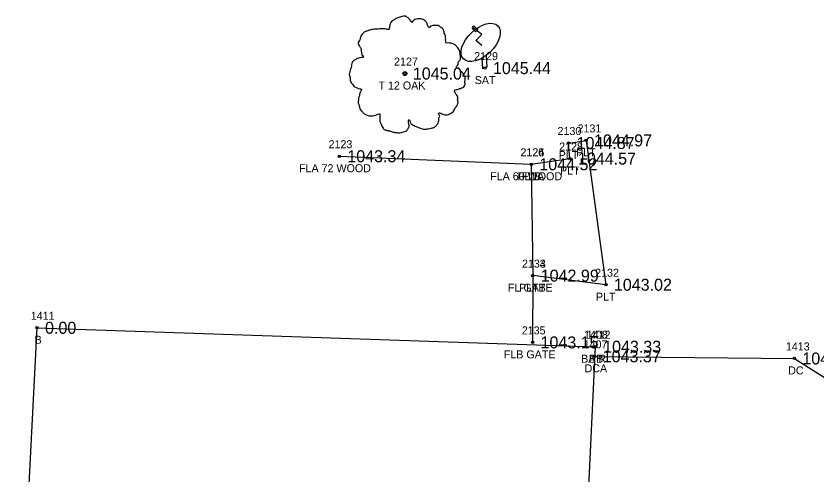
# Model space of a CAD drawing. Extents: x 1578957 to 1581675, y 1115963 to 1120391.
# Drawn here: x 1579631.3 to 1579731.3, y 1117805.4 to 1117862.7 of the extents above; entities that cross this region are included whole.
import ezdxf

# ---------------------------------------------------------------- set-up
doc = ezdxf.new("R2010")
doc.units = 0
for name, color, linetype in [('RD_EX_Bldg', 7, 'Continuous'), ('RD_EX_Bldg_txCode', 7, 'Continuous'), ('RD_EX_BldgApp', 7, 'Continuous'), ('RD_EX_BldgApp_txCode', 7, 'Continuous'), ('RD_EX_Conc', 7, 'Continuous'), ('RD_EX_Conc_txCode', 7, 'Continuous'), ('RD_EX_Fence_Other', 7, 'Continuous'), ('RD_EX_Fence_Other_txCode', 7, 'Continuous'), ('RD_EX_TX_Bldg_ELEV', 7, 'Continuous'), ('RD_EX_TX_BldgApp_ELEV', 7, 'Continuous'), ('RD_EX_TX_Conc_ELEV', 7, 'Continuous'), ('RD_EX_TX_Fence_Other_ELEV', 7, 'Continuous'), ('RD_EX_TX_VEG_ELEV', 7, 'Continuous'), ('RD_EX_VEG', 7, 'Continuous'), ('RD_EX_VEG_txCode', 7, 'Continuous'), ('RD_SMD_Locator', 7, 'Continuous')]:
    doc.layers.add(name, color=color, linetype=linetype)

msp = doc.modelspace()

# ---------------------------------------------------------------- linework, layer by layer
at = {"layer": 'RD_EX_Bldg'}
msp.add_lwpolyline([(1579703.654, 1117821.358), (1579701.175, 1117768.74), (1579631.267, 1117772.317), (1579633.897, 1117823.728), (1579703.654, 1117821.358)], dxfattribs=at)
at = {"layer": 'RD_EX_BldgApp'}
for p, q in [((1579688.717, 1117860.753), (1579688.325, 1117861.141)), ((1579689.503, 1117860.438), (1579688.39, 1117861.273)), ((1579688.568, 1117861.436), (1579688.992, 1117861.07)), ((1579688.601, 1117861.177), (1579688.601, 1117861.177)), ((1579688.716, 1117861.157), (1579688.716, 1117861.157)), ((1579688.993, 1117861.071), (1579688.717, 1117860.753)), ((1579688.736, 1117859.67), (1579689.503, 1117860.438)), ((1579689.503, 1117859.057), (1579688.736, 1117859.67)), ((1579689.503, 1117857.493), (1579689.58, 1117856.15)), ((1579690.04, 1117857.781), (1579690.117, 1117856.323))]:
    msp.add_line(p, q, dxfattribs=at)
msp.add_lwpolyline([(1579695.676, 1117844.189), (1579700.503, 1117844.906), (1579700.337, 1117846.851), (1579702.514, 1117847.178), (1579704.996, 1117829.116), (1579695.851, 1117830.253)], dxfattribs=at)
msp.add_ellipse((1579689.35, 1117859.44), major_axis=(-2.149, -2.072), ratio=0.564687, dxfattribs=at)
msp.add_ellipse((1579688.45, 1117861.285), major_axis=(0.099, 0.164), ratio=0.846225, start_param=6.138676, end_param=9.218032, dxfattribs=at)
at = {"layer": 'RD_EX_Conc'}
msp.add_lwpolyline([(1579703.598, 1117820.153), (1579728.553, 1117819.89), (1579733.569, 1117816.721), (1579737.087, 1117813.155), (1579748.821, 1117810.274), (1579774.526, 1117806.485), (1579776.381, 1117807.018)], dxfattribs=at)
at = {"layer": 'RD_EX_Fence_Other'}
msp.add_lwpolyline([(1579671.678, 1117845.198), (1579695.676, 1117844.189), (1579695.676, 1117844.189), (1579695.851, 1117830.253), (1579695.828, 1117821.899)], dxfattribs=at)
at = {"layer": 'RD_EX_VEG'}
for centre, radius in [((1579679.867, 1117855.546), 0.25), ((1579679.855, 1117855.527), 0.0001)]:
    msp.add_circle(centre, radius, dxfattribs=at)
for points in [[(1579679.999, 1117862.713), (1579679.699, 1117862.738), (1579679.374, 1117862.638), (1579679.124, 1117862.539), (1579678.9, 1117862.464), (1579678.675, 1117862.364), (1579678.375, 1117862.189), (1579678.15, 1117861.989), (1579678.025, 1117861.739), (1579677.975, 1117861.514), (1579677.925, 1117861.239), (1579677.925, 1117861.064), (1579677.8, 1117861.039), (1579677.65, 1117861.064), (1579677.4, 1117861.139), (1579677.15, 1117861.139), (1579676.9, 1117861.139), (1579676.551, 1117861.114), (1579676.201, 1117861.114), (1579675.926, 1117861.064), (1579675.601, 1117861.014), (1579675.226, 1117860.889), (1579674.876, 1117860.764), (1579674.576, 1117860.514), (1579674.327, 1117860.04), (1579674.202, 1117859.69), (1579674.052, 1117859.44), (1579674.202, 1117858.99), (1579674.377, 1117858.64), (1579674.401, 1117858.44), (1579674.476, 1117858.016), (1579674.576, 1117857.791), (1579674.701, 1117857.591), (1579674.626, 1117857.566), (1579674.252, 1117857.516), (1579673.952, 1117857.416), (1579673.527, 1117857.191), (1579673.302, 1117856.966), (1579673.202, 1117856.641), (1579673.177, 1117856.291), (1579673.077, 1117856.091), (1579673.002, 1117855.816), (1579672.977, 1117855.741), (1579672.927, 1117855.417), (1579673.027, 1117854.967), (1579673.052, 1117854.617), (1579673.177, 1117854.392), (1579673.327, 1117854.217), (1579673.502, 1117853.967), (1579673.902, 1117853.742), (1579674.227, 1117853.642), (1579674.426, 1117853.617), (1579674.252, 1117853.118), (1579674.202, 1117852.768), (1579674.077, 1117852.368), (1579674.077, 1117852.293), (1579674.027, 1117851.818), (1579674.177, 1117851.493), (1579674.252, 1117851.119), (1579674.426, 1117850.894), (1579674.701, 1117850.594), (1579675.026, 1117850.369), (1579675.526, 1117850.244), (1579675.926, 1117850.269), (1579676.501, 1117850.444), (1579676.75, 1117850.519), (1579676.725, 1117850.344), (1579676.75, 1117849.969), (1579676.75, 1117849.544), (1579676.9, 1117849.219), (1579677, 1117848.944), (1579677.15, 1117848.695), (1579677.475, 1117848.47), (1579677.875, 1117848.395), (1579678.3, 1117848.245), (1579678.75, 1117848.17), (1579679.249, 1117848.145), (1579679.849, 1117848.295), (1579680.124, 1117848.42), (1579680.224, 1117848.595), (1579680.424, 1117848.969), (1579680.374, 1117849.194), (1579680.399, 1117849.794), (1579680.499, 1117849.619), (1579680.674, 1117849.269), (1579681.174, 1117848.969), (1579681.573, 1117848.795), (1579682.048, 1117848.645), (1579682.348, 1117848.57), (1579682.823, 1117848.645), (1579683.198, 1117848.72), (1579683.572, 1117848.845), (1579683.872, 1117849.119), (1579684.047, 1117849.394), (1579684.097, 1117849.669), (1579684.172, 1117850.044), (1579684.222, 1117850.219)], [(1579684.222, 1117850.219), (1579684.147, 1117850.394), (1579684.097, 1117850.644), (1579684.172, 1117850.619), (1579684.347, 1117850.569), (1579684.622, 1117850.444), (1579684.847, 1117850.369), (1579685.172, 1117850.394), (1579685.447, 1117850.494), (1579685.896, 1117850.769), (1579686.171, 1117851.243), (1579686.446, 1117851.643), (1579686.521, 1117851.968), (1579686.471, 1117852.193), (1579686.446, 1117852.693), (1579686.246, 1117852.943), (1579686.196, 1117853.068), (1579686.096, 1117853.467), (1579686.171, 1117853.517), (1579686.446, 1117853.567), (1579686.821, 1117853.692), (1579687.096, 1117853.817), (1579687.321, 1117853.992), (1579687.396, 1117854.217), (1579687.371, 1117854.617), (1579687.421, 1117855.017), (1579687.346, 1117855.167), (1579687.246, 1117855.317), (1579687.171, 1117855.517), (1579687.021, 1117855.666), (1579686.921, 1117855.816), (1579686.821, 1117855.916), (1579686.696, 1117856.066), (1579686.521, 1117856.191), (1579686.371, 1117856.241), (1579686.321, 1117856.391), (1579686.471, 1117856.591), (1579686.521, 1117856.691), (1579686.546, 1117856.916), (1579686.771, 1117857.266), (1579686.821, 1117857.666), (1579686.771, 1117858.09), (1579686.721, 1117858.365), (1579686.571, 1117858.64), (1579686.371, 1117858.89), (1579686.246, 1117859.065), (1579686.071, 1117859.19), (1579685.747, 1117859.315), (1579685.497, 1117859.365), (1579685.147, 1117859.365), (1579684.947, 1117859.415), (1579684.972, 1117859.465), (1579684.972, 1117859.615), (1579684.972, 1117859.89), (1579684.897, 1117860.339), (1579684.747, 1117860.839), (1579684.747, 1117860.864), (1579684.647, 1117861.114), (1579684.422, 1117861.314), (1579684.247, 1117861.414), (1579684.047, 1117861.539), (1579683.797, 1117861.564), (1579683.498, 1117861.564), (1579683.223, 1117861.514), (1579683.023, 1117861.414), (1579682.848, 1117861.289), (1579682.773, 1117861.439), (1579682.673, 1117861.739), (1579682.623, 1117861.889), (1579682.473, 1117862.064), (1579682.248, 1117862.264), (1579681.798, 1117862.389), (1579681.174, 1117862.314), (1579680.874, 1117862.114), (1579680.724, 1117861.939), (1579680.674, 1117862.064), (1579680.474, 1117862.264), (1579680.374, 1117862.439), (1579680.199, 1117862.564), (1579680.049, 1117862.663), (1579679.949, 1117862.713)]]:
    msp.add_spline(points, degree=3, dxfattribs=at)
at = {"layer": 'RD_SMD_Locator'}
for centre in [(1579679.867, 1117855.546), (1579689.88, 1117856.225), (1579700.337, 1117846.851), (1579702.514, 1117847.178), (1579671.678, 1117845.198), (1579700.503, 1117844.906), (1579695.676, 1117844.189), (1579695.676, 1117844.189), (1579695.676, 1117844.189), (1579695.851, 1117830.253), (1579695.851, 1117830.253), (1579704.996, 1117829.116), (1579633.897, 1117823.728), (1579695.828, 1117821.899), (1579703.654, 1117821.358), (1579703.654, 1117821.358), (1579703.598, 1117820.153), (1579728.553, 1117819.89)]:
    msp.add_circle(centre, 0.15, dxfattribs=at)

# ---------------------------------------------------------------- texts
at = {"layer": 'RD_EX_Bldg_txCode'}
for s, p in [('1411', (1579633.117, 1117824.728)), ('B', (1579633.59, 1117821.728)), ('1408', (1579702.269, 1117822.358)), ('1412', (1579702.591, 1117822.358)), ('BA R', (1579701.898, 1117819.358)), ('BB', (1579702.875, 1117819.358))]:
    msp.add_text(s, height=1, dxfattribs=at).set_placement(p)
at = {"layer": 'RD_EX_BldgApp_txCode'}
for s, p in [('2129', (1579688.534, 1117857.225)), ('SAT', (1579688.597, 1117854.225)), ('2130', (1579698.952, 1117847.851)), ('2131', (1579701.451, 1117848.178)), ('2128', (1579699.157, 1117845.906)), ('2126', (1579694.306, 1117845.189)), ('PLT', (1579699.093, 1117844.851)), ('PLT', (1579701.27, 1117845.178)), ('PLT', (1579699.259, 1117842.906)), ('PLTA', (1579693.944, 1117842.189)), ('2133', (1579694.505, 1117831.253)), ('2132', (1579703.65, 1117830.116)), ('PLTB', (1579694.135, 1117828.253)), ('PLT', (1579703.752, 1117827.116))]:
    msp.add_text(s, height=1, dxfattribs=at).set_placement(p)
at = {"layer": 'RD_EX_Conc_txCode'}
for s, p in [('1407', (1579702.212, 1117821.153)), ('1413', (1579727.49, 1117820.89)), ('DCA', (1579702.33, 1117818.153)), ('DC', (1579727.774, 1117817.89))]:
    msp.add_text(s, height=1, dxfattribs=at).set_placement(p)
at = {"layer": 'RD_EX_Fence_Other_txCode'}
for s, p in [('2123', (1579670.332, 1117846.198)), ('2124', (1579694.33, 1117845.189)), ('2125', (1579694.33, 1117845.189)), ('FLA 72 WOOD', (1579666.639, 1117843.198)), ('FLA 60 WOOD', (1579690.534, 1117842.189)), ('FLB', (1579694.471, 1117842.189)), ('2134', (1579694.505, 1117831.253)), ('FL GATE', (1579692.753, 1117828.253)), ('2135', (1579694.482, 1117822.899)), ('FLB GATE', (1579692.234, 1117819.899))]:
    msp.add_text(s, height=1, dxfattribs=at).set_placement(p)
at = {"layer": 'RD_EX_TX_Bldg_ELEV'}
for s, p in [('0.00', (1579634.897, 1117822.978)), ('1043.33', (1579704.654, 1117820.608)), ('1043.33', (1579704.654, 1117820.608))]:
    msp.add_text(s, height=1.5, dxfattribs=at).set_placement(p)
at = {"layer": 'RD_EX_TX_BldgApp_ELEV'}
for s, p in [('1045.44', (1579690.88, 1117855.475)), ('1044.87', (1579701.337, 1117846.101)), ('1044.97', (1579703.514, 1117846.428)), ('1044.57', (1579701.503, 1117844.156)), ('1044.52', (1579696.676, 1117843.439)), ('1042.99', (1579696.851, 1117829.503)), ('1043.02', (1579705.996, 1117828.366))]:
    msp.add_text(s, height=1.5, dxfattribs=at).set_placement(p)
at = {"layer": 'RD_EX_TX_Conc_ELEV'}
for s, p in [('1043.37', (1579704.598, 1117819.403)), ('1043.19', (1579729.553, 1117819.14))]:
    msp.add_text(s, height=1.5, dxfattribs=at).set_placement(p)
at = {"layer": 'RD_EX_TX_Fence_Other_ELEV'}
for s, p in [('1043.34', (1579672.678, 1117844.448)), ('1044.52', (1579696.676, 1117843.439)), ('1044.52', (1579696.676, 1117843.439)), ('1042.99', (1579696.851, 1117829.503)), ('1043.15', (1579696.828, 1117821.149))]:
    msp.add_text(s, height=1.5, dxfattribs=at).set_placement(p)
at = {"layer": 'RD_EX_TX_VEG_ELEV'}
msp.add_text('1045.04', height=1.5, dxfattribs=at).set_placement((1579680.867, 1117854.796))
at = {"layer": 'RD_EX_VEG_txCode'}
for s, p in [('2127', (1579678.521, 1117856.546)), ('T 12 OAK', (1579676.568, 1117853.546))]:
    msp.add_text(s, height=1, dxfattribs=at).set_placement(p)

doc.saveas('drawing.dxf')
